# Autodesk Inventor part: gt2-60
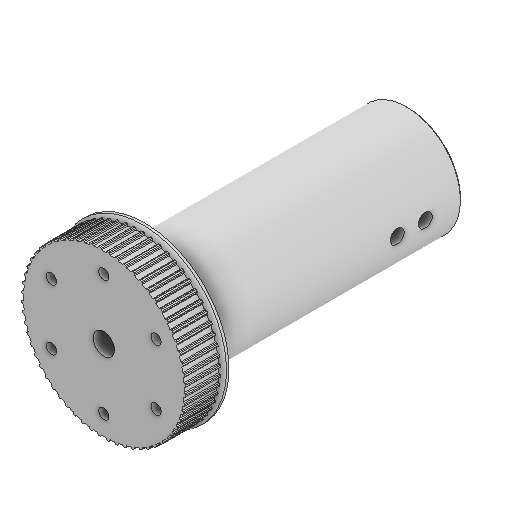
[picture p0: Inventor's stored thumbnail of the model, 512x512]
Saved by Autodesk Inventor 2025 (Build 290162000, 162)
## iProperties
Created: 2025-06
Part Number: gt2-60
Material: Generico
Document SubType Name: Modeling
Designer: Ryzen5700u
Density: 1 g/cm^3
Appearance: Default
Author: Ryzen5700u
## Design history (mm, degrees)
sketch "Schizzo1"
  geometry: C1 r 4.963 at (0, 0); A1 r 18.592 centre (0, 0) between (-0.5, -18.585) and (0.5, -18.585); A2 r 0.65 centre (0, -19) between (0.628, -18.833) and (0.5, -18.585); A3 r 0.2 centre (0.822, -18.782) between (0.628, -18.833) and (0.83, -18.982); A4 r 19 centre (0, 0) between (0.83, -18.982) and (1.158, -18.965); A5 r 0.2 centre (1.146, -18.765) between (1.158, -18.965) and (1.344, -18.796); A6 r 0.65 centre (1.986, -18.896) between (1.445, -18.536) and (1.344, -18.796); A7 r 18.592 centre (0, 0) between (1.445, -18.536) and (2.44, -18.431); A8 r 0.65 centre (1.986, -18.896) between (2.593, -18.664) and (2.44, -18.431); A9 r 0.2 centre (2.78, -18.593) between (2.593, -18.664) and (2.81, -18.791); A10 r 19 centre (0, 0) between (2.81, -18.791) and (3.134, -18.74); A11 r 0.2 centre (3.101, -18.542) between (3.134, -18.74) and (3.301, -18.552); A12 r 0.65 centre (3.95, -18.585) between (3.375, -18.283) and (3.301, -18.552); A13 r 18.592 centre (0, 0) between (3.375, -18.283) and (4.354, -18.075); A14 r 0.65 centre (3.95, -18.585) between (4.53, -18.291) and (4.354, -18.075); A15 r 0.2 centre (4.709, -18.201) between (4.53, -18.291) and (4.759, -18.394); A16 r 19 centre (0, 0) between (4.759, -18.394) and (5.076, -18.309); A17 r 0.2 centre (5.023, -18.117) between (5.076, -18.309) and (5.222, -18.106); A18 r 0.65 centre (5.871, -18.07) between (5.267, -17.83) and (5.222, -18.106); A19 r 18.592 centre (0, 0) between (5.267, -17.83) and (6.219, -17.521); A20 r 0.65 centre (5.871, -18.07) between (6.417, -17.717) and (6.219, -17.521); A21 r 0.2 centre (6.585, -17.609) between (6.417, -17.717) and (6.655, -17.796); A22 r 19 centre (0, 0) between (6.655, -17.796) and (6.962, -17.679); A23 r 0.2 centre (6.889, -17.492) between (6.962, -17.679) and (7.086, -17.461); A24 r 0.65 centre (7.728, -17.357) between (7.102, -17.182) and (7.086, -17.461); A25 r 18.592 centre (0, 0) between (7.102, -17.182) and (8.017, -16.775); A26 r 0.65 centre (7.728, -17.357) between (8.234, -16.95) and (8.017, -16.775); A27 r 0.2 centre (8.39, -16.824) between (8.234, -16.95) and (8.479, -17.003); A28 r 19 centre (0, 0) between (8.479, -17.003) and (8.772, -16.854); A29 r 0.2 centre (8.68, -16.677) between (8.772, -16.854) and (8.873, -16.624); A30 r 0.65 centre (9.5, -16.454) between (8.859, -16.346) and (8.873, -16.624); A31 r 18.592 centre (0, 0) between (8.859, -16.346) and (9.726, -15.845); A32 r 0.65 centre (9.5, -16.454) between (9.961, -15.996) and (9.726, -15.845); A33 r 0.2 centre (10.103, -15.855) between (9.961, -15.996) and (10.21, -16.024); A34 r 19 centre (0, 0) between (10.21, -16.024) and (10.486, -15.845); A35 r 0.2 centre (10.375, -15.678) between (10.486, -15.845) and (10.562, -15.606); A36 r 0.65 centre (11.168, -15.371) between (10.519, -15.33) and (10.562, -15.606); A37 r 18.592 centre (0, 0) between (10.519, -15.33) and (11.329, -14.742); A38 r 0.65 centre (11.168, -15.371) between (11.578, -14.867) and (11.329, -14.742); A39 r 0.2 centre (11.704, -14.712) between (11.578, -14.867) and (11.829, -14.869); A40 r 19 centre (0, 0) between (11.829, -14.869) and (12.084, -14.662); A41 r 0.2 centre (11.957, -14.508) between (12.084, -14.662) and (12.135, -14.416); A42 r 0.65 centre (12.713, -14.12) between (12.064, -14.146) and (12.135, -14.416); A43 r 18.592 centre (0, 0) between (12.064, -14.146) and (12.808, -13.477); A44 r 0.65 centre (12.713, -14.12) between (13.069, -13.575) and (12.808, -13.477); A45 r 0.2 centre (13.178, -13.408) between (13.069, -13.575) and (13.318, -13.551); A46 r 19 centre (0, 0) between (13.318, -13.551) and (13.551, -13.318); A47 r 0.2 centre (13.408, -13.178) between (13.551, -13.318) and (13.575, -13.069); A48 r 0.65 centre (14.12, -12.713) between (13.477, -12.808) and (13.575, -13.069); A49 r 18.592 centre (0, 0) between (13.477, -12.808) and (14.146, -12.064); A50 r 0.65 centre (14.12, -12.713) between (14.416, -12.135) and (14.146, -12.064); A51 r 0.2 centre (14.508, -11.957) between (14.416, -12.135) and (14.662, -12.084); A52 r 19 centre (0, 0) between (14.662, -12.084) and (14.869, -11.829); A53 r 0.2 centre (14.712, -11.704) between (14.869, -11.829) and (14.867, -11.578); A54 r 0.65 centre (15.371, -11.168) between (14.742, -11.329) and (14.867, -11.578); A55 r 18.592 centre (0, 0) between (14.742, -11.329) and (15.33, -10.519); A56 r 0.65 centre (15.371, -11.168) between (15.606, -10.562) and (15.33, -10.519); A57 r 0.2 centre (15.678, -10.375) between (15.606, -10.562) and (15.845, -10.486); A58 r 19 centre (0, 0) between (15.845, -10.486) and (16.024, -10.21); A59 r 0.2 centre (15.855, -10.103) between (16.024, -10.21) and (15.996, -9.961); A60 r 0.65 centre (16.454, -9.5) between (15.845, -9.726) and (15.996, -9.961); A61 r 18.592 centre (0, 0) between (15.845, -9.726) and (16.346, -8.859); A62 r 0.65 centre (16.454, -9.5) between (16.624, -8.873) and (16.346, -8.859); A63 r 0.2 centre (16.677, -8.68) between (16.624, -8.873) and (16.854, -8.772); A64 r 19 centre (0, 0) between (16.854, -8.772) and (17.003, -8.479)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; 361 further points
  constraints: 720 point on circle, 361 centre point
extrude "Estrusione1" new body sketch "Schizzo1" stored distance "d0" = 7; taper "d1" = 0 deg
sketch "Schizzo2"
  geometry: C1 r 19.5 at (0, 0); 1 further point
  constraints: 1 centre point, 1 coincident
  dimensions: "d2" = 39 diameter of C1
extrude "Estrusione2" join sketch "Schizzo2" distance "d3" = 1.5; taper "d4" = 0 deg
sketch "Schizzo3"
  geometry: C1 r 12.5 at (0, 0); 1 further point
  constraints: 1 centre point, 1 coincident
  dimensions: "d5" = 25 diameter of C1
extrude "Estrusione3" join sketch "Schizzo3" distance "d6" = 61; taper "d7" = 0 deg
sketch "Schizzo4"
  geometry: C1 r 12.5 at (0, 0) reference; C2 r 10 at (0, 0); C3 r 14 at (0, 0); 1 further point
  constraints: 2 centre point, 1 coincident
  dimensions: "d23" = 1.5 radial gap between concentric circles of C1 C3
extrude "Estrusione4" join sketch "Schizzo4" distance "d9" = 2; taper "d10" = 0 deg
chamfer "Smusso1" distance "d11" = 0.4; stored, may be unused: second distance "d12" = 2, angle "d13" = 45 deg
sketch "Schizzo5"
  geometry: 1 further point
hole "Foro1" sketch "Schizzo5" at (0, 0) diameter "d14" = 5.5; stored, may be unused: countersink angle "d18" = 90 deg, drill point angle "d20" = 0 deg; dims "d15" = 6, "d16" = 10, "d17" = 5.7, "d19" = 50
sketch "Schizzo6"
  geometry: L1 (12.1, -66)-(-12.1, -66) reference; C1 r 1.6 at (0, -51); C2 r 1.7 at (0, -52) reference; C3 r 1.6 at (0, -57.5); 1 further point
  constraints: 2 centre point
  dimensions: "d37" = 15 distance from line of L1 C1.centre; "d38" = 3.2 diameter of C1; "d39" = 3.2 diameter of C3; "d40" = 6.5 distance of C3.centre C1.centre
extrude "Estrusione5" sketch "Schizzo6" extent not by distance; stored distance "d21" = 0; taper "d22" = 0 deg
fillet "Raccordo1" dims "d24" = 1.5
sketch "Schizzo7"
  geometry: C1 r 12.5 at (0, 0) reference; A1 r 19 centre (0, 0) between (-1.158, -18.965) and (-0.83, -18.982) reference; A2 r 0.2 centre (-0.822, -18.782) between (-0.83, -18.982) and (-0.628, -18.833) reference; A3 r 0.65 centre (0, -19) between (-0.5, -18.585) and (-0.628, -18.833) reference; A4 r 18.592 centre (0, 0) between (-0.5, -18.585) and (0.5, -18.585) reference; A5 r 0.65 centre (0, -19) between (0.628, -18.833) and (0.5, -18.585) reference; A6 r 0.2 centre (0.822, -18.782) between (0.628, -18.833) and (0.83, -18.982) reference; A7 r 19 centre (0, 0) between (0.83, -18.982) and (1.158, -18.965) reference; A8 r 0.2 centre (1.146, -18.765) between (1.158, -18.965) and (1.344, -18.796) reference; A9 r 0.65 centre (1.986, -18.896) between (1.445, -18.536) and (1.344, -18.796) reference; A10 r 18.592 centre (0, 0) between (1.445, -18.536) and (2.44, -18.431) reference; A11 r 0.65 centre (1.986, -18.896) between (2.593, -18.664) and (2.44, -18.431) reference; A12 r 0.2 centre (2.78, -18.593) between (2.593, -18.664) and (2.81, -18.791) reference; A13 r 19 centre (0, 0) between (2.81, -18.791) and (3.134, -18.74) reference; A14 r 0.2 centre (3.101, -18.542) between (3.134, -18.74) and (3.301, -18.552) reference; A15 r 0.65 centre (3.95, -18.585) between (3.375, -18.283) and (3.301, -18.552) reference; A16 r 18.592 centre (0, 0) between (3.375, -18.283) and (4.354, -18.075) reference; A17 r 0.65 centre (3.95, -18.585) between (4.53, -18.291) and (4.354, -18.075) reference; A18 r 0.2 centre (4.709, -18.201) between (4.53, -18.291) and (4.759, -18.394) reference; A19 r 19 centre (0, 0) between (4.759, -18.394) and (5.076, -18.309) reference; A20 r 0.2 centre (5.023, -18.117) between (5.076, -18.309) and (5.222, -18.106) reference; A21 r 0.65 centre (5.871, -18.07) between (5.267, -17.83) and (5.222, -18.106) reference; A22 r 18.592 centre (0, 0) between (5.267, -17.83) and (6.219, -17.521) reference; A23 r 0.65 centre (5.871, -18.07) between (6.417, -17.717) and (6.219, -17.521) reference; A24 r 0.2 centre (6.585, -17.609) between (6.417, -17.717) and (6.655, -17.796) reference; A25 r 19 centre (0, 0) between (6.655, -17.796) and (6.962, -17.679) reference; A26 r 0.2 centre (6.889, -17.492) between (6.962, -17.679) and (7.086, -17.461) reference; A27 r 0.65 centre (7.728, -17.357) between (7.102, -17.182) and (7.086, -17.461) reference; A28 r 18.592 centre (0, 0) between (7.102, -17.182) and (8.017, -16.775) reference; A29 r 0.65 centre (7.728, -17.357) between (8.234, -16.95) and (8.017, -16.775) reference; A30 r 0.2 centre (8.39, -16.824) between (8.234, -16.95) and (8.479, -17.003) reference; A31 r 19 centre (0, 0) between (8.479, -17.003) and (8.772, -16.854) reference; A32 r 0.2 centre (8.68, -16.677) between (8.772, -16.854) and (8.873, -16.624) reference; A33 r 0.65 centre (9.5, -16.454) between (8.859, -16.346) and (8.873, -16.624) reference; A34 r 18.592 centre (0, 0) between (8.859, -16.346) and (9.726, -15.845) reference; A35 r 0.65 centre (9.5, -16.454) between (9.961, -15.996) and (9.726, -15.845) reference; A36 r 0.2 centre (10.103, -15.855) between (9.961, -15.996) and (10.21, -16.024) reference; A37 r 19 centre (0, 0) between (10.21, -16.024) and (10.486, -15.845) reference; A38 r 0.2 centre (10.375, -15.678) between (10.486, -15.845) and (10.562, -15.606) reference; A39 r 0.65 centre (11.168, -15.371) between (10.519, -15.33) and (10.562, -15.606) reference; A40 r 18.592 centre (0, 0) between (10.519, -15.33) and (11.329, -14.742) reference; A41 r 0.65 centre (11.168, -15.371) between (11.578, -14.867) and (11.329, -14.742) reference; A42 r 0.2 centre (11.704, -14.712) between (11.578, -14.867) and (11.829, -14.869) reference; A43 r 19 centre (0, 0) between (11.829, -14.869) and (12.084, -14.662) reference; A44 r 0.2 centre (11.957, -14.508) between (12.084, -14.662) and (12.135, -14.416) reference; A45 r 0.65 centre (12.713, -14.12) between (12.064, -14.146) and (12.135, -14.416) reference; A46 r 18.592 centre (0, 0) between (12.064, -14.146) and (12.808, -13.477) reference; A47 r 0.65 centre (12.713, -14.12) between (13.069, -13.575) and (12.808, -13.477) reference; A48 r 0.2 centre (13.178, -13.408) between (13.069, -13.575) and (13.318, -13.551) reference; A49 r 19 centre (0, 0) between (13.318, -13.551) and (13.551, -13.318) reference; A50 r 0.2 centre (13.408, -13.178) between (13.551, -13.318) and (13.575, -13.069) reference; A51 r 0.65 centre (14.12, -12.713) between (13.477, -12.808) and (13.575, -13.069) reference; A52 r 18.592 centre (0, 0) between (13.477, -12.808) and (14.146, -12.064) reference; A53 r 0.65 centre (14.12, -12.713) between (14.416, -12.135) and (14.146, -12.064) reference; A54 r 0.2 centre (14.508, -11.957) between (14.416, -12.135) and (14.662, -12.084) reference; A55 r 19 centre (0, 0) between (14.662, -12.084) and (14.869, -11.829) reference; A56 r 0.2 centre (14.712, -11.704) between (14.869, -11.829) and (14.867, -11.578) reference; A57 r 0.65 centre (15.371, -11.168) between (14.742, -11.329) and (14.867, -11.578) reference; A58 r 18.592 centre (0, 0) between (14.742, -11.329) and (15.33, -10.519) reference; A59 r 0.65 centre (15.371, -11.168) between (15.606, -10.562) and (15.33, -10.519) reference; A60 r 0.2 centre (15.678, -10.375) between (15.606, -10.562) and (15.845, -10.486) reference; A61 r 19 centre (0, 0) between (15.845, -10.486) and (16.024, -10.21) reference; A62 r 0.2 centre (15.855, -10.103) between (16.024, -10.21) and (15.996, -9.961) reference; A63 r 0.65 centre (16.454, -9.5) between (15.845, -9.726) and (15.996, -9.961) reference; A64 r 18.592 centre (0, 0) between (15.845, -9.726) and (16.346, -8.859) reference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; 1 further point
extrude "Estrusione6" join sketch "Schizzo7" distance "d25" = 1; taper "d26" = 0 deg
sketch "Schizzo8"
  geometry: 4 further points
  constraints: 1 coincident, 1 vertical alignment, 1 other
hole "Foro2" sketch "Schizzo8" at (0, 14) diameter "d27" = 2.4; stored, may be unused: countersink angle "d31" = 90 deg, drill point angle "d33" = 118 deg; dims "d28" = 6, "d29" = 4.4, "d30" = 2.3, "d32" = 7
pattern_circular "Serie circolare1" dims angle "d35" = 360 deg
sketch "Schizzo9"
  geometry: 2 further points
hole "Foro3" sketch "Schizzo9" at (0, 0) diameter "d41" = 5; stored, may be unused: countersink angle "d45" = 90 deg, drill point angle "d47" = 118 deg; dims "d42" = 6, "d43" = 5.5, "d44" = 2, "d46" = 8
fillet "Raccordo2" dims "d48" = 0.9
node "Solido1"
node "Riferimento2"
node "Riferimento3"
node "Linea chiusa proiettata1"
